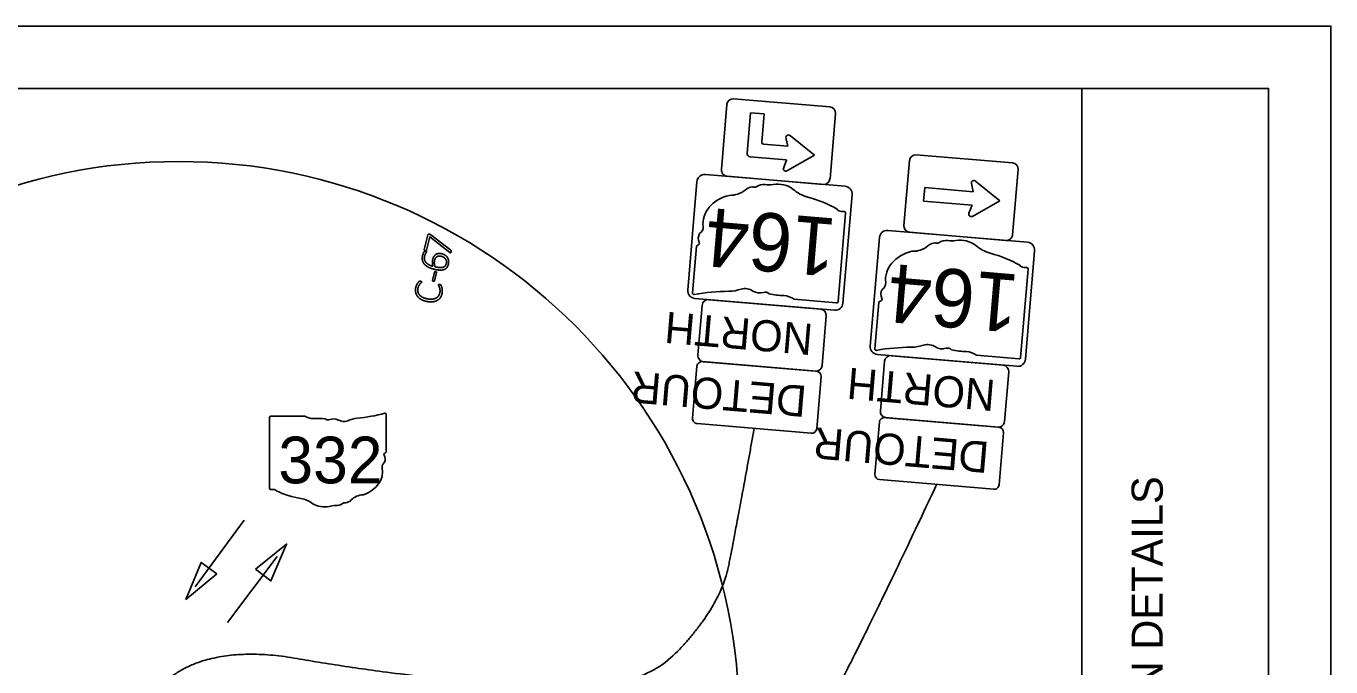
# Model space of a CAD drawing. Extents: x -740 to 1519, y 0 to 440.
# Drawn here: x 470.5 to 680, y 337.1 to 440 of the extents above; entities that cross this region are included whole.
import ezdxf

# ---------------------------------------------------------------- set-up
doc = ezdxf.new("R2010")
doc.units = 0
for name, color, linetype in [('Default', 7, 'Continuous'), ('GM_X_County_Road_Text', 7, 'Continuous'), ('GM_X_Minor_Lake', 7, 'Continuous'), ('GM_X_Minor_River', 7, 'Continuous'), ('GM_X_Unincorporated_Location', 7, 'Continuous'), ('SH_Border', 7, 'Continuous'), ('SH_Cut_Line', 7, 'Continuous'), ('SH_Data', 7, 'Continuous')]:
    doc.layers.add(name, color=color, linetype=linetype)

msp = doc.modelspace()

# ---------------------------------------------------------------- linework, layer by layer
at = {"layer": 'Default'}
for p, q in [((497.64, 349.91), (505.52, 360.63)), ((510.82, 354.81), (502.81, 344.18))]:
    msp.add_line(p, q, dxfattribs=at)
for points in [[(507.32, 352.76), (512.32, 356.8), (509.81, 350.88)], [(501.12, 352), (496.16, 347.9), (498.6, 353.85)]]:
    msp.add_lwpolyline(points, close=True, dxfattribs=at)
at = {"layer": 'GM_X_County_Road_Text'}
for p, q in [((509.57, 377.14), (509.57, 365.75)), ((515.25, 377.33), (509.76, 377.33)), ((528.32, 371.66), (528.32, 377.61)), ((528.32, 371.66), (528.32, 371.66))]:
    msp.add_line(p, q, dxfattribs=at)
for centre, major_axis, start_param, end_param in [((509.79, 377.16), (0.217, 0), 1.712693, 3.28349), ((516.56, 378.65), (2.11, 0), 4.042523, 4.731795), ((521.64, 392.85), (19.88, 0), 4.814394, 5.042369), ((528.11, 377.64), (0.209, 0), 6.141152, 7.989035), ((517.25, 370.94), (7.56, 0), 1.404758, 1.657858), ((518.97, 377.22), (0.608, 0), 3.836095, 5.185415), ((519.86, 375.9), (1.26, 0), 0.950623, 2.079405), ((521.49, 377.71), (1.52, 0), 4.081561, 5.145723), ((524.18, 373.86), (4, 0), 1.699011, 2.107814), ((528.27, 371.22), (0.323, 0), 1.883978, 3.671073), ((526.22, 370.47), (1.94, 0), 5.934695, 6.695948), ((528.1, 371.64), (0.223, 0), 5.05454, 6.418171), ((522.76, 368.41), (4.97, 0), 5.101752, 6.440018), ((529.07, 369.17), (1.41, 0), 2.387724, 3.262537), ((509.79, 365.73), (0.219, 0), 3.00124, 4.508301), ((509.82, 366.89), (1.67, 0), 4.665946, 4.897461), ((510.16, 365.09), (0.603, 0), 0.519207, 1.627899), ((517.78, 375.32), (14.36, 0), 4.195997, 4.488961), ((524.85, 362.56), (2.72, 0), 1.647645, 2.488434), ((513.5, 360.64), (4.49, 0), 0.823519, 1.323587), ((518.36, 365.04), (2.85, 0), 4.026481, 4.996735), ((520, 361.1), (2.34, 0), 1.495662, 1.94098), ((520.21, 364.19), (1.52, 0), 4.691044, 5.507374), ((521.58, 363.08), (0.428, 0), 1.147584, 2.315152), ((521.4, 364.65), (1.61, 0), 4.937069, 5.64225)]:
    msp.add_ellipse(centre, major_axis=major_axis, ratio=0.8, start_param=start_param, end_param=end_param, dxfattribs=at)
at = {"layer": 'GM_X_Minor_Lake'}
for p, q in [((628.86, 418.03), (613.42, 419.34)), ((612.34, 418.43), (611.45, 407.97)), ((628.88, 406.48), (629.77, 416.95)), ((623.01, 415.06), (626.84, 411.93)), ((614.6, 411.87), (614.79, 414.05)), ((614.79, 414.05), (622.57, 413.39)), ((622.57, 413.39), (622.28, 414.7)), ((622.39, 411.21), (614.6, 411.87)), ((621.88, 409.96), (622.39, 411.21)), ((626.84, 411.93), (622.47, 409.44)), ((612.36, 406.89), (627.8, 405.57))]:
    msp.add_line(p, q, dxfattribs=at)
for centre, radius, start, end in [((613.33, 418.34), 1, 85.1336, 175.1336), ((628.78, 417.03), 1, 355.1336, 85.1336), ((622.69, 414.79), 0.417, 40.1241, 192.3382), ((622.27, 409.81), 0.417, 157.929, 299.7224), ((612.44, 407.88), 1, 175.1336, 265.1336), ((627.89, 406.57), 1, 265.1336, 355.1336)]:
    msp.add_arc(centre, radius, start, end, dxfattribs=at)
at = {"layer": 'GM_X_Minor_River'}
for p, q in [((582.13, 416.96), (583.01, 427.42)), ((584.09, 428.33), (599.54, 427.03)), ((586.82, 426.06), (586.27, 419.52)), ((589, 425.88), (586.82, 426.06)), ((588.62, 421.36), (589, 425.88)), ((600.45, 425.95), (599.57, 415.48)), ((592.5, 422.13), (592.8, 420.7)), ((597.06, 419.24), (593.23, 422.37)), ((592.8, 420.7), (588.9, 421.03)), ((592.76, 416.8), (597.06, 419.24)), ((586.69, 419.02), (592.61, 418.52)), ((586.69, 419.02), (586.69, 419.02)), ((592.61, 418.52), (592.08, 417.15)), ((598.49, 414.57), (583.04, 415.88)), ((600.89, 395.78), (602.08, 409.96)), ((578.11, 404.57), (577.48, 397.15)), ((578.11, 404.57), (578.11, 404.57)), ((630.18, 386.77), (631.39, 400.95)), ((580.12, 396.05), (598.05, 394.54)), ((593.8, 396.13), (600.63, 395.55)), ((578.36, 387.17), (579.04, 395.14)), ((607.41, 395.58), (606.78, 388.17)), ((607.42, 395.58), (607.41, 395.58)), ((598.96, 393.46), (598.29, 385.49)), ((597.21, 384.57), (579.28, 386.09)), ((607.66, 378.18), (608.33, 386.15)), ((609.42, 387.06), (627.35, 385.54)), ((623.1, 387.13), (629.93, 386.55)), ((628.26, 384.46), (627.58, 376.49)), ((626.5, 375.57), (608.57, 377.1))]:
    msp.add_line(p, q, dxfattribs=at)
for points in [[(576.73, 397.59), (578.2, 415.03)], [(579.56, 416.17), (601.98, 414.28)], [(603.12, 412.93), (601.64, 395.49)], [(608.87, 407.18), (631.29, 405.27)], [(606.03, 388.61), (607.52, 406.04)], [(632.43, 403.92), (630.94, 386.49)], [(600.29, 394.35), (577.87, 396.24)], [(597.41, 384.56), (579.08, 386.1)], [(629.59, 385.35), (607.17, 387.26)], [(578.21, 385.37), (577.51, 377)], [(597.43, 375.32), (598.14, 383.69)], [(578.24, 376.14), (596.57, 374.59)], [(607.5, 376.39), (606.79, 368.02)], [(626.7, 375.56), (608.37, 377.12)], [(626.72, 366.32), (627.43, 374.69)], [(607.52, 367.15), (625.85, 365.59)]]:
    msp.add_lwpolyline(points, dxfattribs=at)
for centre, radius, start, end in [((584.01, 427.33), 1, 85.176, 175.176), ((599.46, 426.03), 1, 355.176, 85.176), ((588.93, 421.34), 0.312, 175.176, 265.176), ((592.91, 422.1), 0.417, 40.1761, 175.1776), ((586.73, 419.49), 0.469, 175.176, 265.176), ((583.13, 416.87), 1, 175.176, 265.176), ((592.49, 417.12), 0.417, 175.1776, 310.1759), ((579.45, 414.92), 1.25, 85.176, 175.176), ((598.57, 415.57), 1, 265.176, 355.176), ((601.87, 413.03), 1.25, 355.176, 85.176), ((608.76, 405.94), 1.25, 85.1336, 175.1336), ((631.18, 404.03), 1.25, 355.1336, 85.1336), ((577.98, 397.49), 1.25, 175.176, 265.176), ((580.03, 395.06), 1, 85.176, 175.176), ((597.97, 393.54), 1, 355.176, 85.176), ((600.4, 395.59), 1.25, 265.176, 355.176), ((607.28, 388.5), 1.25, 175.1336, 265.1336), ((579.01, 385.31), 0.8, 85.176, 175.176), ((579.36, 387.08), 1, 175.176, 265.176), ((609.33, 386.07), 1, 85.1336, 175.1336), ((627.27, 384.54), 1, 355.1336, 85.1336), ((629.7, 386.59), 1.25, 265.1336, 355.1336), ((597.3, 385.57), 1, 265.176, 355.176), ((597.34, 383.76), 0.8, 355.176, 85.176), ((608.65, 378.1), 1, 175.1336, 265.1336), ((578.3, 376.94), 0.8, 175.176, 265.176), ((596.64, 375.39), 0.8, 265.176, 355.176), ((608.3, 376.32), 0.8, 85.1336, 175.1336), ((626.59, 376.57), 1, 265.1336, 355.1336), ((626.63, 374.76), 0.8, 355.1336, 85.1336), ((607.59, 367.95), 0.8, 175.1336, 265.1336), ((625.92, 366.39), 0.8, 265.1336, 355.1336)]:
    msp.add_arc(centre, radius, start, end, dxfattribs=at)
for centre, major_axis, start_param, end_param in [((585.38, 408.03), (-6.19, 0.52), 5.101752, 6.440018), ((583.38, 415.54), (-3.39, 0.29), 1.647645, 2.488434), ((587.46, 412.57), (-2, 0.17), 4.937069, 5.64225), ((587.4, 414.54), (-0.533, 0.045), 1.147584, 2.315152), ((589, 413.02), (-1.89, 0.16), 4.691044, 5.507374), ((589.58, 416.84), (-2.92, 0.25), 1.495662, 1.94098), ((591.22, 411.77), (-3.55, 0.3), 4.026481, 4.996735), ((597.73, 416.74), (-5.6, 0.47), 0.823519, 1.323587), ((590.86, 398.9), (-17.88, 1.51), 4.195997, 4.488961), ((601.41, 410.84), (-0.751, 0.063), 0.519207, 1.627899), ((601.65, 408.56), (-2.08, 0.18), 4.665946, 4.897461), ((601.81, 410.01), (-0.273, 0.023), 3.00124, 4.508301), ((580.85, 405.83), (-2.42, 0.2), 5.934695, 6.695948), ((577.44, 407.75), (-1.76, 0.15), 2.387724, 3.262537), ((578.39, 404.57), (-0.278, 0.023), 5.05454, 6.418171), ((578.21, 405.11), (-0.402, 0.034), 1.883978, 3.671073), ((612.7, 406.55), (-3.39, 0.29), 1.647645, 2.488434), ((616.77, 403.58), (-2, 0.17), 4.937069, 5.64225), ((616.71, 405.55), (-0.533, 0.045), 1.147584, 2.315152), ((618.31, 404.03), (-1.89, 0.16), 4.691044, 5.507374), ((618.89, 407.85), (-2.92, 0.25), 1.495662, 1.94098), ((620.53, 402.77), (-3.55, 0.3), 4.026481, 4.996735), ((627.05, 407.74), (-5.6, 0.48), 0.823519, 1.323587), ((614.69, 399.04), (-6.19, 0.53), 5.101752, 6.440018), ((620.16, 389.9), (-17.88, 1.52), 4.195997, 4.488961), ((630.72, 401.83), (-0.751, 0.064), 0.519207, 1.627899), ((630.96, 399.56), (-2.08, 0.18), 4.665946, 4.897461), ((631.12, 401.01), (-0.273, 0.023), 3.00124, 4.508301), ((606.75, 398.77), (-1.76, 0.15), 2.387724, 3.262537), ((577.74, 397.1), (-0.26, 0.022), 6.141152, 7.989035), ((584.2, 377.47), (-24.77, 2.09), 4.814394, 5.042369), ((583.04, 401.4), (-4.98, 0.42), 1.699011, 2.107814), ((585.98, 396.32), (-1.89, 0.16), 4.081561, 5.145723), ((588.2, 398.39), (-1.57, 0.13), 0.950623, 2.079405), ((589.17, 396.66), (-0.757, 0.064), 3.836095, 5.185415), ((591.97, 404.3), (-9.42, 0.8), 1.404758, 1.657858), ((592.03, 394.62), (-2.62, 0.22), 4.042523, 4.731795), ((607.52, 396.12), (-0.402, 0.034), 1.883978, 3.671073), ((610.16, 396.84), (-2.42, 0.21), 5.934695, 6.695948), ((600.62, 395.77), (-0.271, 0.023), 1.712693, 3.28349), ((607.69, 395.59), (-0.278, 0.024), 5.05454, 6.418171), ((607.04, 388.11), (-0.26, 0.022), 6.141152, 7.989035), ((613.48, 368.48), (-24.77, 2.11), 4.814394, 5.042369), ((612.34, 392.41), (-4.98, 0.42), 1.699011, 2.107814), ((615.28, 387.33), (-1.89, 0.16), 4.081561, 5.145723), ((617.5, 389.4), (-1.57, 0.13), 0.950623, 2.079405), ((618.47, 387.67), (-0.757, 0.064), 3.836095, 5.185415), ((621.27, 395.3), (-9.42, 0.8), 1.404758, 1.657858), ((621.33, 385.62), (-2.62, 0.22), 4.042523, 4.731795), ((629.91, 386.77), (-0.271, 0.023), 1.712693, 3.28349)]:
    msp.add_ellipse(centre, major_axis=major_axis, ratio=0.8, start_param=start_param, end_param=end_param, dxfattribs=at)
at = {"layer": 'GM_X_Unincorporated_Location'}
for p, q in [((534.43, 404.1), (535.02, 406.47)), ((535.23, 406.58), (535.23, 406.58)), ((535.49, 406.45), (538.67, 404.02)), ((537.18, 403.01), (537.18, 403.01)), ((537.24, 403.43), (537.24, 403.43)), ((535.76, 399.15), (536.06, 400.49)), ((536.38, 400.42), (536.08, 399.08)), ((536.24, 400.55), (536.24, 400.55)), ((536.9, 398.5), (536.9, 398.5))]:
    msp.add_line(p, q, dxfattribs=at)
msp.add_lwpolyline([(538.55, 403.61), (535.3, 406.13), (534.78, 404.02)], dxfattribs=at)
for points in [[(535.02, 406.47), (535.03, 406.52), (535.05, 406.54)], [(535.05, 406.54), (535.06, 406.57), (535.09, 406.58)], [(535.09, 406.58), (535.11, 406.59), (535.15, 406.59)], [(535.15, 406.59), (535.18, 406.59), (535.23, 406.58)], [(535.23, 406.58), (535.27, 406.57), (535.3, 406.56)], [(535.3, 406.56), (535.33, 406.55), (535.36, 406.53)], [(535.36, 406.53), (535.39, 406.52), (535.42, 406.5)], [(535.42, 406.5), (535.46, 406.48), (535.49, 406.45)], [(534.15, 403.16), (534.07, 402.82), (534.1, 402.55)], [(534.1, 402.55), (534.13, 402.27), (534.25, 402.05)], [(534.22, 403.39), (534.18, 403.28), (534.15, 403.16)], [(534.31, 403.6), (534.26, 403.51), (534.22, 403.39)], [(534.4, 403.76), (534.36, 403.7), (534.31, 403.6)], [(534.47, 403.84), (534.45, 403.82), (534.4, 403.76)], [(534.43, 404.05), (534.43, 404.07), (534.43, 404.1)], [(534.46, 404.01), (534.44, 404.03), (534.43, 404.05)], [(534.47, 402.45), (534.39, 402.71), (534.47, 403.03)], [(534.5, 403.97), (534.47, 403.98), (534.46, 404.01)], [(534.51, 403.86), (534.49, 403.86), (534.47, 403.84)], [(534.47, 403.03), (534.51, 403.2), (534.56, 403.32)], [(534.74, 401.98), (534.55, 402.19), (534.47, 402.45)], [(534.58, 403.94), (534.53, 403.95), (534.5, 403.97)], [(534.55, 403.87), (534.53, 403.87), (534.51, 403.86)], [(534.6, 403.87), (534.57, 403.87), (534.55, 403.87)], [(534.56, 403.32), (534.61, 403.44), (534.66, 403.52)], [(534.71, 403.94), (534.65, 403.92), (534.58, 403.94)], [(534.66, 403.86), (534.62, 403.87), (534.6, 403.87)], [(534.72, 403.84), (534.69, 403.85), (534.66, 403.86)], [(534.66, 403.52), (534.71, 403.6), (534.75, 403.66)], [(534.78, 404.02), (534.77, 403.96), (534.71, 403.94)], [(534.76, 403.82), (534.75, 403.83), (534.72, 403.84)], [(534.75, 403.66), (534.78, 403.71), (534.79, 403.75)], [(534.79, 403.79), (534.78, 403.81), (534.76, 403.82)], [(534.79, 403.75), (534.8, 403.77), (534.79, 403.79)], [(535.77, 402.5), (535.73, 402.34), (535.73, 402.19)], [(536, 403.06), (535.85, 402.85), (535.77, 402.5)], [(536.34, 403.37), (536.15, 403.27), (536, 403.06)], [(536.04, 402.1), (536.05, 402.24), (536.08, 402.38)], [(536.08, 402.38), (536.14, 402.62), (536.24, 402.77)], [(536.24, 402.77), (536.35, 402.92), (536.49, 402.99)], [(536.77, 403.48), (536.54, 403.47), (536.34, 403.37)], [(536.49, 402.99), (536.63, 403.06), (536.81, 403.06)], [(537.24, 403.43), (537, 403.49), (536.77, 403.48)], [(536.81, 403.06), (536.98, 403.06), (537.18, 403.01)], [(537.18, 403.01), (537.35, 402.97), (537.52, 402.88)], [(537.72, 403.24), (537.49, 403.37), (537.24, 403.43)], [(537.52, 402.88), (537.68, 402.79), (537.8, 402.64)], [(538.1, 402.89), (537.94, 403.1), (537.72, 403.24)], [(537.8, 402.64), (537.92, 402.49), (537.97, 402.3)], [(537.97, 402.3), (538.02, 402.11), (537.97, 401.87)], [(538.31, 402.39), (538.25, 402.68), (538.1, 402.89)], [(538.29, 401.74), (538.37, 402.1), (538.31, 402.39)], [(538.6, 403.57), (538.58, 403.58), (538.55, 403.61)], [(538.65, 403.57), (538.63, 403.56), (538.6, 403.57)], [(538.69, 403.62), (538.67, 403.58), (538.65, 403.57)], [(538.67, 404.02), (538.71, 403.99), (538.73, 403.97)], [(538.73, 403.73), (538.71, 403.66), (538.69, 403.62)], [(538.73, 403.97), (538.75, 403.94), (538.75, 403.91)], [(538.75, 403.84), (538.75, 403.79), (538.73, 403.73)], [(538.75, 403.91), (538.76, 403.88), (538.75, 403.84)], [(534.25, 402.05), (534.36, 401.82), (534.55, 401.64)], [(534.55, 401.64), (534.74, 401.47), (534.97, 401.33)], [(535.21, 401.64), (534.93, 401.78), (534.74, 401.98)], [(534.97, 401.33), (535.2, 401.19), (535.47, 401.1)], [(535.81, 401.41), (535.49, 401.49), (535.21, 401.64)], [(535.47, 401.1), (535.74, 401), (536.01, 400.94)], [(535.73, 402.19), (535.72, 402.03), (535.73, 401.89)], [(535.73, 401.89), (535.73, 401.75), (535.76, 401.63)], [(535.76, 401.63), (535.78, 401.51), (535.81, 401.41)], [(536.01, 400.94), (536.32, 400.86), (536.59, 400.83)], [(536.04, 401.83), (536.03, 401.96), (536.04, 402.1)], [(536.09, 401.56), (536.06, 401.69), (536.04, 401.83)], [(536.06, 400.49), (536.06, 400.51), (536.08, 400.53)], [(536.08, 400.53), (536.09, 400.54), (536.11, 400.55)], [(536.16, 401.33), (536.11, 401.44), (536.09, 401.56)], [(536.11, 400.55), (536.13, 400.56), (536.16, 400.56)], [(536.92, 401.21), (536.6, 401.23), (536.16, 401.33)], [(536.16, 400.56), (536.2, 400.56), (536.24, 400.55)], [(536.24, 400.55), (536.33, 400.53), (536.36, 400.5)], [(536.36, 400.5), (536.39, 400.46), (536.38, 400.42)], [(536.59, 400.83), (536.86, 400.79), (537.09, 400.8)], [(537.46, 401.27), (537.24, 401.2), (536.92, 401.21)], [(537.09, 400.8), (537.33, 400.81), (537.52, 400.86)], [(537.79, 401.49), (537.67, 401.34), (537.46, 401.27)], [(537.52, 400.86), (537.72, 400.92), (537.87, 401.03)], [(537.97, 401.87), (537.91, 401.64), (537.79, 401.49)], [(537.87, 401.03), (538.02, 401.15), (538.12, 401.32)], [(538.12, 401.32), (538.23, 401.5), (538.29, 401.74)], [(533.03, 397.91), (533.06, 398.1), (533.13, 398.27)], [(533.13, 398.27), (533.2, 398.44), (533.28, 398.58)], [(533.28, 398.58), (533.36, 398.72), (533.45, 398.82)], [(533.53, 398.28), (533.43, 398.1), (533.39, 397.83)], [(533.45, 398.82), (533.54, 398.93), (533.59, 398.96)], [(533.74, 398.58), (533.63, 398.46), (533.53, 398.28)], [(533.59, 398.96), (533.64, 399), (533.66, 399.01)], [(533.66, 399.01), (533.69, 399.01), (533.71, 399.02)], [(533.71, 399.02), (533.74, 399.02), (533.77, 399.02)], [(533.92, 398.77), (533.84, 398.7), (533.74, 398.58)], [(533.77, 399.02), (533.8, 399.02), (533.84, 399.01)], [(533.84, 399.01), (533.88, 399), (533.92, 398.99)], [(533.92, 398.99), (533.95, 398.98), (533.97, 398.96)], [(534.01, 398.89), (534, 398.84), (533.92, 398.77)], [(533.97, 398.96), (533.99, 398.95), (534, 398.93)], [(534, 398.93), (534.01, 398.91), (534.01, 398.89)], [(535.78, 399.07), (535.75, 399.11), (535.76, 399.15)], [(535.9, 399.02), (535.81, 399.04), (535.78, 399.07)], [(536.03, 399.02), (535.99, 399), (535.9, 399.02)], [(536.08, 399.08), (536.07, 399.04), (536.03, 399.02)], [(536.7, 398.46), (536.71, 398.48), (536.72, 398.49)], [(536.75, 398.31), (536.7, 398.41), (536.7, 398.46)], [(536.72, 398.49), (536.73, 398.5), (536.75, 398.5)], [(536.75, 398.5), (536.77, 398.51), (536.81, 398.51)], [(536.85, 398.05), (536.8, 398.21), (536.75, 398.31)], [(536.81, 398.51), (536.85, 398.51), (536.9, 398.5)], [(536.9, 398.5), (536.93, 398.49), (536.96, 398.48)], [(536.96, 398.48), (536.99, 398.47), (537.01, 398.46)], [(537.01, 398.46), (537.03, 398.45), (537.05, 398.44)], [(537.05, 398.44), (537.07, 398.42), (537.09, 398.39)], [(537.09, 398.39), (537.12, 398.35), (537.17, 398.24)], [(537.17, 398.24), (537.22, 398.12), (537.26, 397.95)], [(533.06, 397.16), (532.96, 397.51), (533.03, 397.91)], [(533.39, 396.52), (533.15, 396.81), (533.06, 397.16)], [(533.39, 397.83), (533.34, 397.54), (533.41, 397.27)], [(534.02, 396.04), (533.63, 396.24), (533.39, 396.52)], [(533.41, 397.27), (533.49, 397), (533.69, 396.79)], [(533.69, 396.79), (533.88, 396.57), (534.2, 396.41)], [(534.91, 395.75), (534.4, 395.84), (534.02, 396.04)], [(534.2, 396.41), (534.52, 396.26), (534.96, 396.18)], [(534.96, 396.18), (535.37, 396.11), (535.71, 396.14)], [(535.71, 396.14), (536.05, 396.18), (536.3, 396.31)], [(536.3, 396.31), (536.55, 396.44), (536.71, 396.67)], [(537.03, 396.42), (536.83, 396.13), (536.53, 395.95)], [(536.71, 396.67), (536.87, 396.91), (536.93, 397.23)], [(536.94, 397.69), (536.91, 397.9), (536.85, 398.05)], [(536.93, 397.23), (536.98, 397.49), (536.94, 397.69)], [(537.29, 397.11), (537.22, 396.72), (537.03, 396.42)], [(537.26, 397.95), (537.3, 397.78), (537.32, 397.57)], [(537.32, 397.57), (537.33, 397.36), (537.29, 397.11)], [(535.82, 395.72), (535.41, 395.66), (534.91, 395.75)], [(536.53, 395.95), (536.23, 395.77), (535.82, 395.72)]]:
    msp.add_open_spline(points, degree=2, dxfattribs=at)
at = {"layer": 'SH_Border'}
msp.add_line((640, 10), (640, 430), dxfattribs=at)
msp.add_lwpolyline([(30, 430), (670, 430), (670, 10), (30, 10)], close=True, dxfattribs=at)
at = {"layer": 'SH_Cut_Line'}
msp.add_lwpolyline([(0, 0), (680, 0), (680, 440), (0, 440)], close=True, dxfattribs=at)
at = {"layer": 'SH_Data'}
msp.add_circle((495, 328.25), 90, dxfattribs=at)
for points in [[(587.4, 375.37), (584.62, 359.99), (581.97, 346.71), (567.83, 331.99), (528.05, 335.95), (499.96, 340.86), (492.83, 334.73)], [(378.35, 365.83), (385, 348.06), (402, 338.57), (434.58, 327.18), (475.36, 319.62), (495.67, 317.59), (498.24, 330.34)], [(616.69, 366.37), (606.43, 344.47), (594.88, 322.35), (565.19, 321.69), (536.27, 327.08), (513, 334.3), (500.41, 335.45), (496.86, 335.66), (492.35, 331.47)]]:
    msp.add_open_spline(points, degree=2, dxfattribs=at)

# ---------------------------------------------------------------- texts
at = {"layer": 'GM_X_County_Road_Text'}
msp.add_text('332', height=7.5, dxfattribs=at).set_placement((510.99, 366.55))
at = {"layer": 'GM_X_Minor_River'}
for s, height, rotation, p in [('164', 9.375, 175.176, (600.85, 409.05)), ('164', 9.375, 175.1336, (630.16, 400.05)), ('NORTH', 5, 175.176, (596.98, 392.12)), ('DETOUR', 5, 175.176, (595.97, 382.17)), ('NORTH', 5, 175.1336, (626.27, 383.12)), ('DETOUR', 5, 175.1336, (625.26, 373.17))]:
    msp.add_text(s, height=height, rotation=rotation, dxfattribs=at).set_placement(p)
at = {"layer": 'SH_Data'}
msp.add_text('MAINTENANCE OF TRAFFIC - DETOUR INTERSECTION DETAILS', height=5, rotation=90, dxfattribs=at).set_placement((653, 162.26))

doc.saveas('drawing.dxf')
